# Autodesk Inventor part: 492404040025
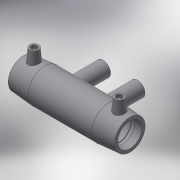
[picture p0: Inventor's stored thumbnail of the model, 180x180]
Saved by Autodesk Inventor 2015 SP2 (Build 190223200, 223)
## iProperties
Created: 2017-06
Part Number: 492404040025
Material: Generic
Description: PLASSON REDUCING TEE WITH TWO OUTLETS 40X25X25X40
Document SubType Name: Modeling
Designer: KIM
Mass: 57.3761 g
Surface Area: 241.06 cm^2
Volume: 57.3761 cm^3
Density: 1 g/cm^3
Appearance: Default
Author: KIM
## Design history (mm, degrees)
derived "492404.ipt"
feature "Solid1::492404.ipt"
tag "TaggingFeature1"
body "Solid1"
other parameters: "d0" = 176, "d2" = 56, "d3" = 46, "d4" = 35.2, "d5" = 50.4, "d6" = 38, "d8" = 168 deg, "d10" = 18.4, "d11" = 6.13333, "d23" = 56, "d29" = 46, "d30" = 15, "d31" = 70.4, "d34" = 5 deg, "d41" = 4, "d42" = 14, "d43" = 0, "d48" = -72, "d49" = 25, "d51" = 0, "d62" = 72, "d74" = -72, "d84" = 25, "d85" = 57, "d86" = 28.5, "d90" = 0, "d91" = 3, "d92" = 0, "L_" = 176, "L_1" = 46, "D_" = 56, "A_" = 46, "d_2" = 12, "H_" = 72, "L_2" = 57, "d_1" = 25
